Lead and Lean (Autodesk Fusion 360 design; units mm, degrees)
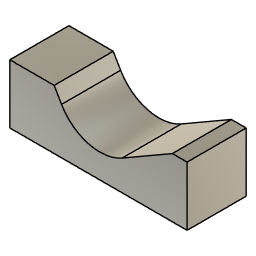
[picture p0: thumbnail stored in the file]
sketch "Sketch1" plane through (0, 0, 0) normal (0, 1, 0) x axis (1, 0, 0)
  line L1 (38.1, 0) -> (-38.1, 0)
  line L2 (-38.1, -25.4) -> (-38.1, 0)
  line L3 (-19.05, -25.4) -> (-38.1, -25.4)
  line L4 (-15.875, -19.9007) -> (-19.05, -25.4)
  line L5 (31.75, -25.4) -> (10.1478, -12.928)
  line L6 (38.1, -25.4) -> (31.75, -25.4)
  line L7 (38.1, 0) -> (38.1, -25.4)
  arc A1 centre (0.6228, -29.4257) radius 19.05 clockwise from (-15.875, -19.9007) to (10.1478, -12.928)
  point P1 (0, 0)
  point P2 (-38.1, 0)
  point P4 (-38.1, -25.4)
  point P3 (38.1, 0)
  point P9 (31.75, -25.4)
  point P10 (38.1, -25.4)
  point P5 (-19.05, -25.4)
  horizontal L1
  midpoint P1 L1
  perpendicular L1 L2
  perpendicular L2 L3
  tangent L4 A1
  perpendicular L4 L5
  horizontal L6
  vertical L7
  collinear L3 L6
  tangent A1 L5
  dimension "d1" angle L3 L4 = 120
  dimension "d2" radius A1 = 19.05
  dimension "d3" distance P2 P4 = 25.4
  dimension "d4" distance P2 P3 = 76.2
  dimension "d5" distance P9 P10 = 6.35
  dimension "d6" distance P4 P5 = 19.05
extrude "Extrude1" new body sketch "Sketch1" distance 25.4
